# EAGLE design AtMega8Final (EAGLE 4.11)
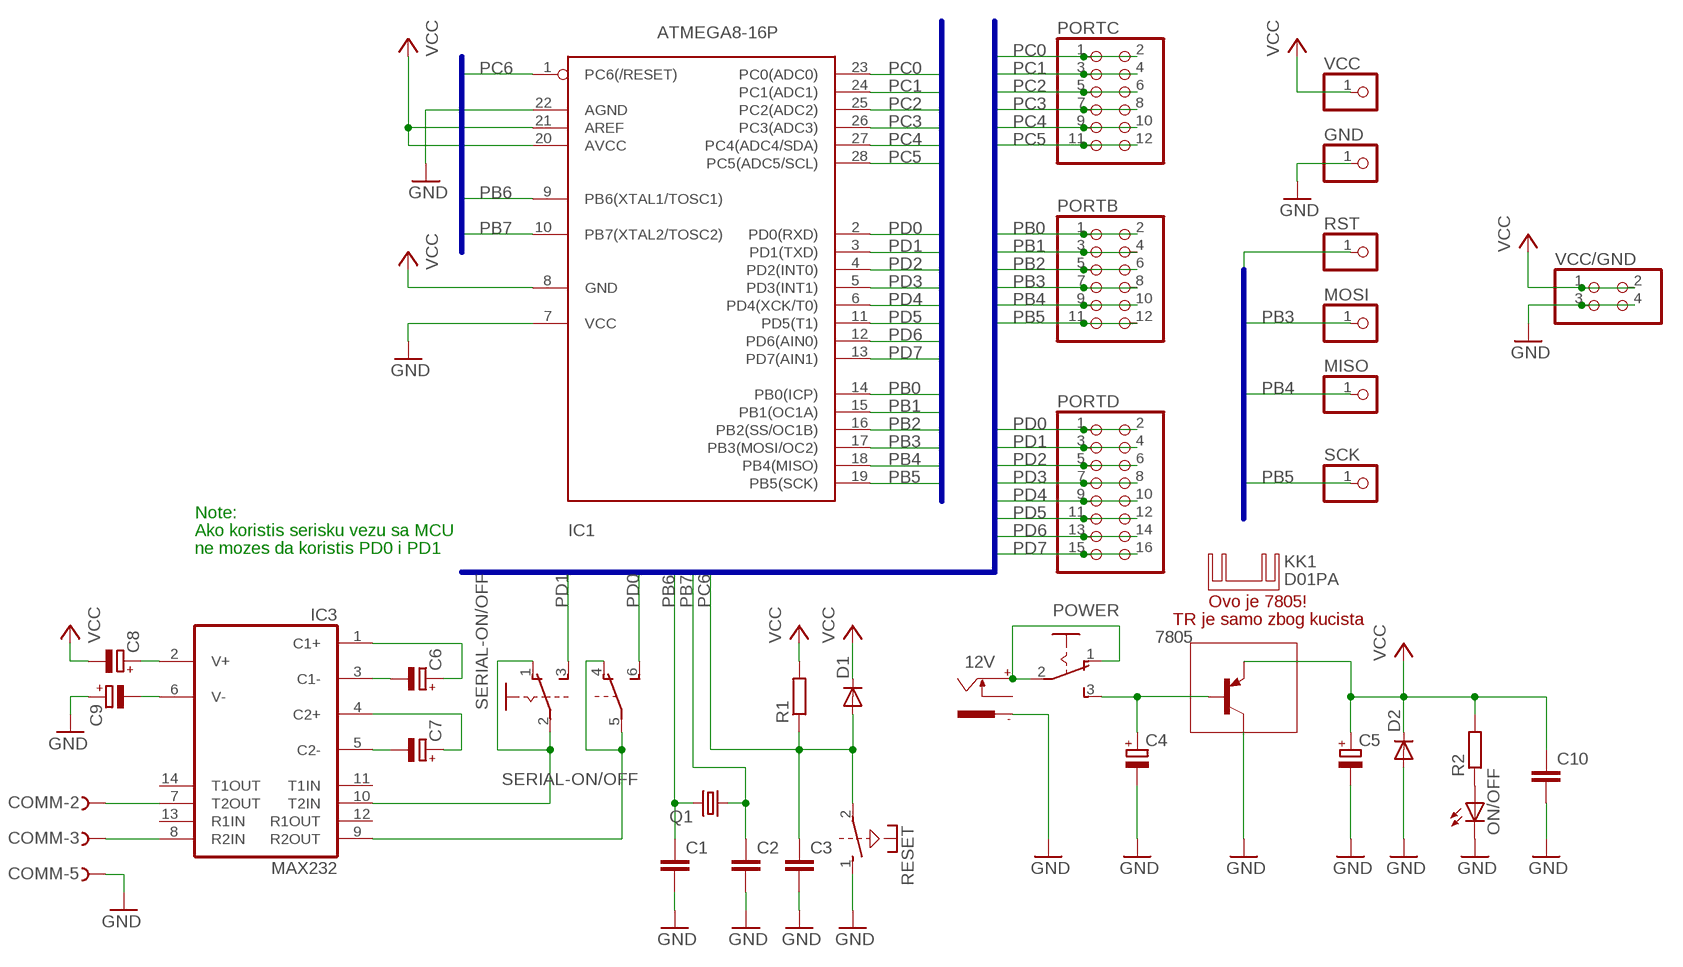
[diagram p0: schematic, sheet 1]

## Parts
12V  737992-55  [737992-5]
7805  -PNP-TO220V  [TO220V]
C1  C-EU025-025X050  [C025-025X050]
C2  C-EU025-025X050  [C025-025X050]
C3  C-EU025-025X050  [C025-025X050]
C4  CPOL-EUE5-6  [E5-6]
C5  CPOL-EUE5-6  [E5-6]
C6  CPOL-EUE5-6  [E5-6]
C7  CPOL-EUE5-6  [E5-6]
C8  CPOL-EUE5-6  [E5-6]
C9  CPOL-EUE5-6  [E5-6]
C10  C-EU025-025X050  [C025-025X050]
COMM  F09HPS  [F09HP]
D1  DIODE-DO35-10  [DO35-10]
D2  DIODE-DO34-7  [DO34-7]
GND  PINHD-1X1  [1X01]
IC1  ATMEGA8-16P  [DIL28-3]
IC3  MAX232  [DIL16]
KK1  D01PA  [D01PA]
MISO  PINHD-1X1  [1X01]
MOSI  PINHD-1X1  [1X01]
ON/OFF  LED5MM  [LED5MM]
PORTB  PINHD-2X6  [2X06]
PORTC  PINHD-2X6  [2X06]
PORTD  PINHD-2X8  [2X08]
POWER  255SB  [255SB]
Q1  CRYTALHC49U70  [HC49U70]
R1  R-EU_0204/7  [0204/7]
R2  R-EU_0204/7  [0204/7]
RESET  PVA1R  [PVA1R]
RST  PINHD-1X1  [1X01]
SCK  PINHD-1X1  [1X01]
SERIAL-ON/OFF  A68-A31  [A68-A31]
VCC  PINHD-1X1  [1X01]
VCC/GND  PINHD-2X2  [2X02]

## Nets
GND: 12V.-1 7805.2(C) C1.2 C2.2 C3.2 C4.- C5.- C9.+ C10.2 COMM.5 D2.A GND.1 IC1.7(VCC) IC1.22(AGND) ON/OFF.K(C) RESET.1(1:S) VCC/GND.3 VCC/GND.4
N$4: 12V.+ POWER.1(O) POWER.2(P)
N$5: 7805.1(B) C4.+ POWER.3(S)
N$6: ON/OFF.A R2.1
N$7: C6.- IC3.3(C1-)
N$8: C6.+ IC3.1(C1+)
N$9: C7.+ IC3.4(C2+)
N$10: C7.- IC3.5(C2-)
N$11: C8.+ IC3.2(V+)
N$12: C9.- IC3.6(V-)
N$13: IC3.9(R2OUT) SERIAL-ON/OFF.4(B:O) SERIAL-ON/OFF.5(B:P)
N$16: IC3.10(T2IN) SERIAL-ON/OFF.1(A:O) SERIAL-ON/OFF.2(A:P)
N$19: COMM.2 IC3.7(T2OUT)
N$20: COMM.3 IC3.8(R2IN)
PB0: IC1.14(PB0(ICP)) PORTB.1 PORTB.2
PB1: IC1.15(PB1(OC1A)) PORTB.3 PORTB.4
PB2: IC1.16(PB2(SS/OC1B)) PORTB.5 PORTB.6
PB3: IC1.17(PB3(MOSI/OC2)) MOSI.1 PORTB.7 PORTB.8
PB4: IC1.18(PB4(MISO)) MISO.1 PORTB.9 PORTB.10
PB5: IC1.19(PB5(SCK)) PORTB.11 PORTB.12 SCK.1
PB6: C1.1 IC1.9(PB6(XTAL1/TOSC1)) Q1.2
PB7: C2.1 IC1.10(PB7(XTAL2/TOSC2)) Q1.1
PC0: IC1.23(PC0(ADC0)) PORTC.1 PORTC.2
PC1: IC1.24(PC1(ADC1)) PORTC.3 PORTC.4
PC2: IC1.25(PC2(ADC2)) PORTC.5 PORTC.6
PC3: IC1.26(PC3(ADC3)) PORTC.7 PORTC.8
PC4: IC1.27(PC4(ADC4/SDA)) PORTC.9 PORTC.10
PC5: IC1.28(PC5(ADC5/SCL)) PORTC.11 PORTC.12
PC6: C3.1 D1.A IC1.1(PC6(/RESET)) R1.1 RESET.2(1:P) RST.1
PD0: IC1.2(PD0(RXD)) PORTD.1 PORTD.2 SERIAL-ON/OFF.6(B:S)
PD1: IC1.3(PD1(TXD)) PORTD.3 PORTD.4 SERIAL-ON/OFF.3(A:S)
PD2: IC1.4(PD2(INT0)) PORTD.5 PORTD.6
PD3: IC1.5(PD3(INT1)) PORTD.7 PORTD.8
PD4: IC1.6(PD4(XCK/T0)) PORTD.9 PORTD.10
PD5: IC1.11(PD5(T1)) PORTD.11 PORTD.12
PD6: IC1.12(PD6(AIN0)) PORTD.13 PORTD.14
PD7: IC1.13(PD7(AIN1)) PORTD.15 PORTD.16
VCC: 7805.3(E) C5.+ C8.- C10.1 D1.C D2.C IC1.8(GND) IC1.20(AVCC) IC1.21(AREF) R1.2 R2.2 VCC.1 VCC/GND.1 VCC/GND.2
Unconnected: 12V.-2 12V.K COMM.1 COMM.4 COMM.6 COMM.7 COMM.8 COMM.9 IC3.11(T1IN) IC3.12(R1OUT) IC3.13(R1IN) IC3.14(T1OUT) RESET.3(2:S) RESET.4(2:P)

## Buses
B$1
B$2
B$3
B$4

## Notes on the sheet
- Note:
- Ako koristis serisku vezu sa MCU
- ne mozes da koristis PD0 i PD1
- Ovo je 7805!
- TR je samo zbog kucista

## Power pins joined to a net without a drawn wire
GND: IC3.15(GND)
VCC: IC3.16(VCC)

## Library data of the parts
12V = con-conrad:737992-55: FEMALE PRINT CONNECTOR DIN 45323 (34V/3A), ROKA, distributor Conrad
7805 = transistor:*-PNP-: PNP Transistror
C1-C3 C10 = rcl:C-EU: CAPACITOR, European symbol
C4-C9 = rcl:CPOL-EU: POLARIZED CAPACITOR, European symbol
COMM = con-subd:F09?S: SUB-D
D1 D2 = diode:DIODE-: DIODE
GND MISO MOSI RST SCK VCC = pinhead:PINHD-1X1: PIN HEADER
IC1 = avr:ATMEGA8*P: MICROCONTROLLER 8 Kbytes FLASH 1 kbytes SRAM 512 bytes EEPROM USART 4-channel 10 bit ADC 2-channel 8 bit ADC
IC3 = maxim:MAX232: RS232 TRANSEIVER
KK1 = heatsink:D01PA: HEATSINK
ON/OFF = led:LED: LED
PORTB PORTC = pinhead:PINHD-2X6: PIN HEADER
PORTD = pinhead:PINHD-2X8: PIN HEADER
POWER = switch:255SB: SLIDING SWITCH distributor Buerklin, 11G810
Q1 = crystal:CRYTAL: CRYSTAL
R1 R2 = rcl:R-EU_: RESISTOR, European symbol
RESET = switch-misc:PVA1R: ITT SWITCH
SERIAL-ON/OFF = switch:A68-A31: SLIDING SWITCH Siemens, distributor Buerklin, 11G766
VCC/GND = pinhead:PINHD-2X2: PIN HEADER

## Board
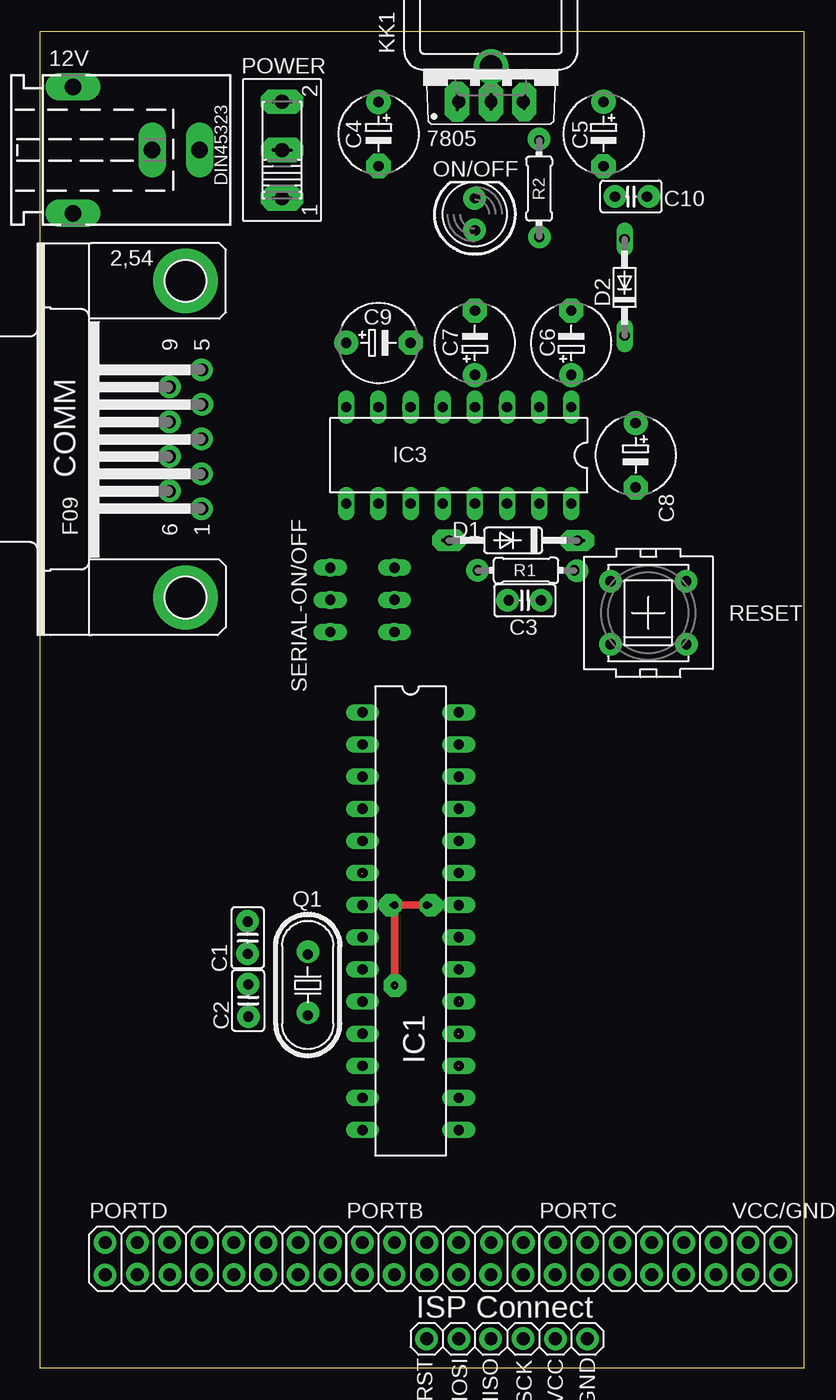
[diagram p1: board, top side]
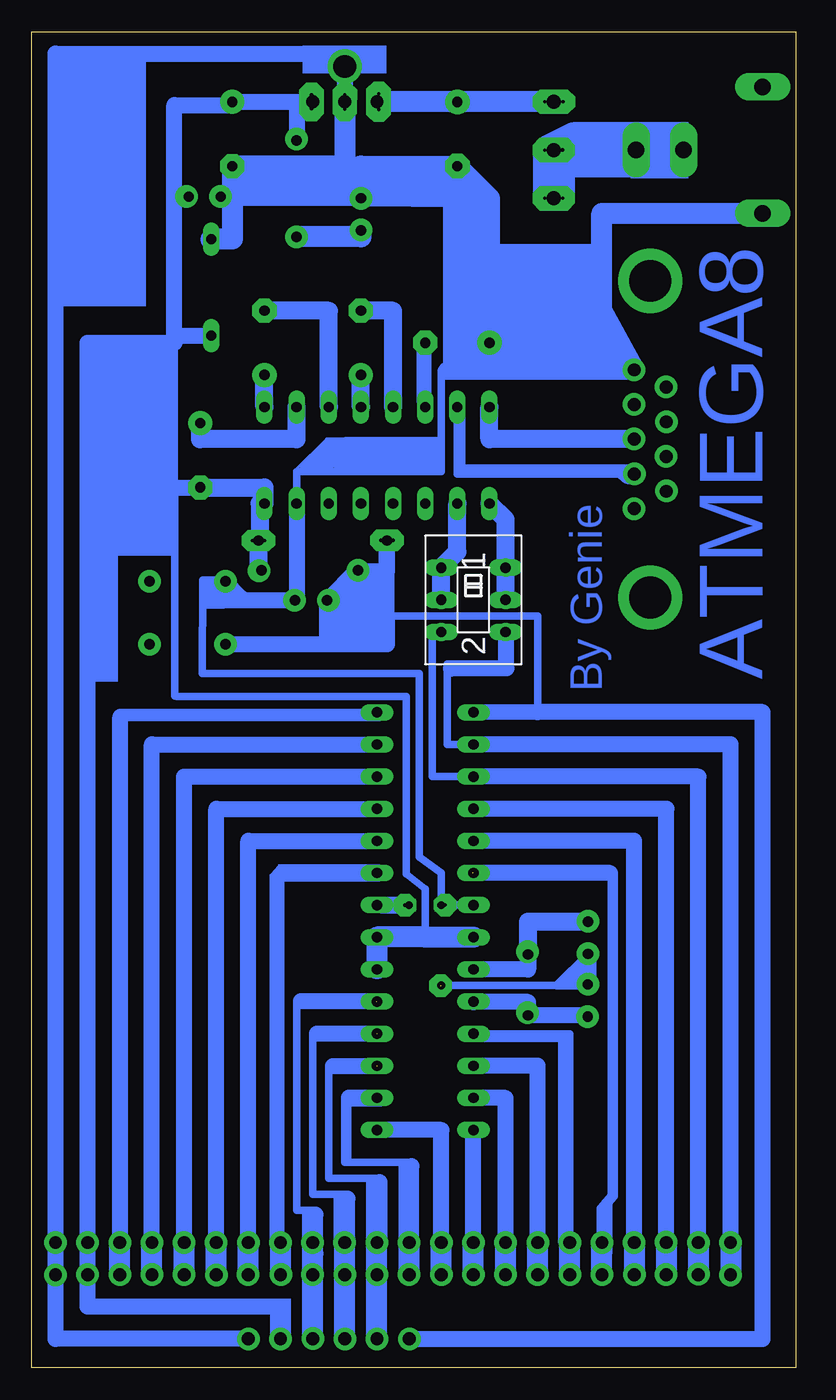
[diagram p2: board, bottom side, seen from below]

Size 60.4 x 105.63 mm. Coordinates in mm from the lower left corner, seen from the top.
Outline: 0,0 60.4,0 60.4,105.63 0,105.63 0,0
Copper layers (1*16): Top 0.035mm / dielectric 1.5mm / Bottom 0.035mm
Design rules "default": minimum track width 10mil, minimum drill 24mil, track to track 8mil, track to pad 8mil, pad to pad 8mil, via to via 8mil, smd to smd 8mil, copper to edge 40mil, drill to drill 8mil, minimum pad ring 10mil, minimum via ring 8mil, stop-mask expansion 4mil, vias tented up to drill 0mil, thermal gap 10mil
vRestrict: area 3.8,5.9 to 24.1,11.3; area 39.5,5.9 to 54.9,11.3; area 28.7,0.8 to 45,3.7

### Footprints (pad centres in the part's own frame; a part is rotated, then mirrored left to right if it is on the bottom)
737992-5 = drill 1.3 pad 2.184 long: + 0,10; -1 5,0; -2 -5,0; K 0,6.25
TO220V = drill 1.016 long: 1 -2.54,-2.54; 2 0,-2.54; 3 2.54,-2.54
C025-025X050 = drill 0.813 octagon: 1 -1.27,0; 2 1.27,0
E5-6 = drill 0.813 pad 1.905 round: + -2.54,0 | drill 0.813 pad 1.905 octagon: - 2.54,0
F09HP = drill 1.016 octagon: 1 -5.486,-1.27; 2 -2.743,-1.27; 3 0,-1.27; 4 2.743,-1.27; 5 5.486,-1.27; 6 -4.115,1.27; 7 -1.372,1.27; 8 1.372,1.27; 9 4.115,1.27 | drill 3.302 pad 5.08 round: G1 -12.522,0; G2 12.522,0
DO35-10 = drill 0.813 long: A 5.08,0; C -5.08,0
DO34-7 = drill 0.813 long: A 3.81,0; C -3.81,0
1X01 = drill 1.016 octagon: 1 0,0
DIL28-3 = drill 0.813 long: 1 -16.51,-3.81; 2 -13.97,-3.81; 3 -11.43,-3.81; 4 -8.89,-3.81; 5 -6.35,-3.81; 6 -3.81,-3.81; 7 -1.27,-3.81; 8 1.27,-3.81; 9 3.81,-3.81; 10 6.35,-3.81; 11 8.89,-3.81; 12 11.43,-3.81; 13 13.97,-3.81; 14 16.51,-3.81; 15 16.51,3.81; 16 13.97,3.81; 17 11.43,3.81; 18 8.89,3.81; 19 6.35,3.81; 20 3.81,3.81; 21 1.27,3.81; 22 -1.27,3.81; 23 -3.81,3.81; 24 -6.35,3.81; 25 -8.89,3.81; 26 -11.43,3.81; 27 -13.97,3.81; 28 -16.51,3.81
DIL16 = drill 0.813 long: 1 -8.89,-3.81; 2 -6.35,-3.81; 3 -3.81,-3.81; 4 -1.27,-3.81; 5 1.27,-3.81; 6 3.81,-3.81; 7 6.35,-3.81; 8 8.89,-3.81; 9 8.89,3.81; 10 6.35,3.81; 11 3.81,3.81; 12 1.27,3.81; 13 -1.27,3.81; 14 -3.81,3.81; 15 -6.35,3.81; 16 -8.89,3.81
D01PA = drill 1.803 pad 2.54 round: B 0,-1.016
LED5MM = drill 0.813 octagon: A -1.27,0; K 1.27,0
2X06 = drill 1.016 octagon: 1 -6.35,-1.27; 2 -6.35,1.27; 3 -3.81,-1.27; 4 -3.81,1.27; 5 -1.27,-1.27; 6 -1.27,1.27; 7 1.27,-1.27; 8 1.27,1.27; 9 3.81,-1.27; 10 3.81,1.27; 11 6.35,-1.27; 12 6.35,1.27
2X08 = drill 1.016 octagon: 1 -8.89,-1.27; 2 -8.89,1.27; 3 -6.35,-1.27; 4 -6.35,1.27; 5 -3.81,-1.27; 6 -3.81,1.27; 7 -1.27,-1.27; 8 -1.27,1.27; 9 1.27,-1.27; 10 1.27,1.27; 11 3.81,-1.27; 12 3.81,1.27; 13 6.35,-1.27; 14 6.35,1.27; 15 8.89,-1.27; 16 8.89,1.27
255SB = drill 1.118 long: 1 -3.81,0; 2 0,0; 3 3.81,0
HC49U70 = drill 0.813 round: 1 -2.413,0; 2 2.413,0
0204/7 = drill 0.813 octagon: 1 -3.81,0; 2 3.81,0
PVA1R = drill 0.813 octagon: 1 -2.997,2.489; 2 -2.997,-2.489; 3 2.997,2.489; 4 2.997,-2.489
A68-A31 = drill 0.813 long: 1 -2.54,-2.54; 2 0,-2.54; 3 2.54,-2.54; 4 -2.54,2.54; 5 0,2.54; 6 2.54,2.54
2X02 = drill 1.016 octagon: 1 -1.27,-1.27; 2 -1.27,1.27; 3 1.27,-1.27; 4 1.27,1.27

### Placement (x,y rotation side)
12V  2.63,96.27 270 top
7805  35.65,102.62 0 top
C1  16.43,34 270 top
C2  16.46,29.04 90 top
C3  38.33,60.67 0 top
C4  26.76,97.54 270 top
C5  44.54,97.54 270 top
C6  42,81.03 90 top
C7  34.38,81.03 90 top
C8  47.08,72.14 270 top
C9  26.76,81.03 0 top
C10  46.72,92.59 180 top
COMM  11.52,73.41 90 top
D1  37.4,65.41 180 top
D2  46.21,85.41 90 top
GND  43.27,2.29 0 top
IC1  29.3,35.31 270 top
IC3  33.11,72.14 180 top
KK1  35.65,103.89 0 top
MISO  35.65,2.29 0 top
MOSI  33.11,2.29 0 top
ON/OFF  34.38,91.19 90 top
PORTB  31.84,8.64 0 top
PORTC  47.08,8.64 0 top
PORTD  14.06,8.64 0 top
POWER  19.14,96.27 90 top
Q1  21.17,30.27 90 top
R1  38.42,63.04 0 top
R2  39.46,93.22 90 top
RESET  48.09,59.68 0 top
RST  30.57,2.29 0 top
SCK  38.19,2.29 0 top
SERIAL-ON/OFF  25.49,60.71 270 bottom
VCC  40.73,2.29 0 top
VCC/GND  57.24,8.64 0 top

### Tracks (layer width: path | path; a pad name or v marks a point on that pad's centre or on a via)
GND  (via drill 0.25 pad 1.78, 0.61)  (1 unrouted)
  Top 0.61: v28.03,30.23 v28.03,36.58 v30.57,36.58
  Bottom 0.406: VCC/GND.3 VCC/GND.4
  Bottom 0.61: 35.65,95 34.38,95 | COMM.5 12.82,78.94 | IC3.15 39.46,70.87 28.03,70.87 28.03,78.57 24.22,78.57 24.22,78.9 | 44.54,92.53 44.71,92.53 | C3.2 39.6,60.64 39.46,60.64 | 45.06,62.2 45.06,62.17 RESET.1 45.2,62.17 45.2,62.27 46.87,62.27 46.91,54.9 29.77,54.9 29.79,40.39 28.03,39.12 v28.03,36.58 IC1.7 | 16.46,30.29 16.58,30.29 | 16.46,30.29 C2.2 | 16.43,30.29 16.46,30.29 | C1.2 18.93,30.23 v28.03,30.23 | v30.57,36.58 IC1.22
  Bottom 1.27: COMM.5 24.22,78.9 C9.+ | IC3.15 39.46,60.64 | C3.2 45.06,60.67 45.06,62.17 | C1.2 16.43,30.29 | GND.1 58.51,2.29 VCC/GND.3 VCC/GND.4 58.51,103.89 35.65,103.89 7805.2
  Bottom 1.676: 7805.2 35.65,95 C5.- 44.54,92.53 44.54,89.23 D2.A | 12V.-1 15.33,91.27 15.33,83.57 12.82,78.94 | C9.+ 24.22,92.46 C4.- 34.38,95 ON/OFF.K | C10.2 44.71,92.59 44.71,92.53
  other vias: 28.08,30.21
N$1
  Bottom 1.27: 45.11,62.15 45.11,62.11 43.86,60.87
N$2
  Bottom 1.27: 34.63,63.07 34.66,63.07 36.98,60.74
N$3
  Bottom 1.27: 12.69,70.51 13.32,70.51 13.57,70.77
N$4
  Bottom 1.27: POWER.1 19.07,92.46 19.05,92.47 19.14,92.56 POWER.2
  Bottom 1.676: 12V.+ POWER.2
N$5
  Bottom 1.676: POWER.3 C4.+ 7805.1
N$6
  Bottom 0.61: ON/OFF.A 34.38,89.41
  Bottom 1.676: 34.37,89.92 ON/OFF.A | 34.38,89.41 R2.1
N$7
  Bottom 1.422: C6.- 36.92,83.57 IC3.3
N$8
  Bottom 1.422: IC3.1 C6.+
N$9
  Bottom 1.422: IC3.4 C7.+
N$10
  Bottom 1.422: C7.- 31.84,83.57 IC3.5
N$11
  Bottom 1.422: IC3.2 39.46,73.41 47.08,73.41 C8.+
N$12
  Bottom 1.016: IC3.6 C9.-
N$13
  Bottom 0.61: IC3.9
  Bottom 1.422: SERIAL-ON/OFF.5 SERIAL-ON/OFF.4 22.95,67.06 IC3.9
N$14
  Bottom 1.27: 29.81,92.44 34.49,92.44 34.49,92.49
N$15
  Bottom 1.27: 53.49,9.89 53.4,9.89 53.4,51.46
N$16
  Bottom 0.61: IC3.10 26.71,68.33
  Bottom 1.422: IC3.10 26.76,64.52 SERIAL-ON/OFF.1 SERIAL-ON/OFF.2
N$17
  Bottom 1.27: 22.91,58.09 22.88,58.09 22.88,55.3 27.25,55.3 27.25,55.27
N$18
  Bottom 1.27: 28.66,72.94 35.64,72.94 37.16,71.41
N$19
  Bottom 0.61: COMM.2 26.76,70.67 IC3.7
N$20
  Bottom 1.422: COMM.3 24.22,73.41 IC3.8
N$21
  Bottom 1.27: 19.18,96.26 17.61,97.82 12.49,97.82
N$22
  Bottom 1.27: 19.18,96.21 17.7,94.73 12.74,94.73
N$23  (via drill 0.25 pad 1.78)
  other vias: 2.62,101.3
N$24  (via drill 0.25 pad 1.78)
  other vias: 2.6,91.28
N$25  (via drill 0.25 pad 1.78)
  other vias: 8.87,96.29
N$26  (via drill 0.25 pad 1.78)
  other vias: 12.63,96.28
N$27  (via drill 0.25 pad 1.93)
  other vias: 18.45,96.27
N$28  (via drill 0.25 pad 1.93)
  other vias: 19.86,96.27
N$29  (via drill 0.25 pad 1.93)
  other vias: 19.12,96.27
N$30  (via drill 0.25 pad 1.93)
  other vias: 18.42,100.09
N$31  (via drill 0.25 pad 1.93)
  other vias: 19.85,100.09
N$32  (via drill 0.25 pad 1.93)
  other vias: 19.13,100.09
N$33  (via drill 0.25 pad 1.93)
  other vias: 19.85,92.46
N$34  (via drill 0.25 pad 1.93)
  other vias: 18.43,92.45
N$35  (via drill 0.25 pad 1.93)
  other vias: 19.11,92.45
N$36  (via drill 0.25 pad 1.93)
  other vias: 26.76,100.08
N$37  (via drill 0.25 pad 1.93)
  other vias: 26.76,95
N$38  (via drill 0.25 pad 1.93)
  other vias: 32.98,100.71
N$39  (via drill 0.25 pad 1.93)
  other vias: 32.98,99.48
N$40  (via drill 0.25 pad 1.93)
  other vias: 32.98,100.17
N$41  (via drill 0.25 pad 1.93)
  other vias: 35.65,100.64
N$42  (via drill 0.25 pad 1.93)
  other vias: 35.66,99.52
N$43  (via drill 0.25 pad 1.93)
  other vias: 35.66,100.12
N$44  (via drill 0.25 pad 1.93)
  other vias: 38.28,100.64
N$45  (via drill 0.25 pad 1.93)
  other vias: 38.28,99.53
N$46  (via drill 0.25 pad 1.93)
  other vias: 38.28,100.1
N$47  (via drill 0.25 pad 1.78)
  other vias: 39.46,97.15
N$48  (via drill 0.25 pad 1.78)
  other vias: 44.53,100.1
N$49  (via drill 0.25 pad 1.78)
  other vias: 44.54,94.98
N$50  (via drill 0.25 pad 1.78)
  other vias: 45.46,92.61
N$51  (via drill 0.25 pad 1.78)
  other vias: 48.14,92.59
N$52  (via drill 0.25 pad 1.78)
  other vias: 34.37,92.45
N$53  (via drill 0.25 pad 1.78)
  other vias: 34.37,89.97
N$54  (via drill 0.25 pad 1.78)
  other vias: 39.48,89.41
N$55  (via drill 0.25 pad 1.78)
  other vias: 24.22,81.03
N$56  (via drill 0.25 pad 1.78)
  other vias: 29.29,81.01
N$57  (via drill 0.25 pad 1.78)
  other vias: 34.39,83.58
N$58  (via drill 0.25 pad 1.78)
  other vias: 41.99,83.59
N$59  (via drill 0.25 pad 1.78)
  other vias: 41.99,78.51
N$60  (via drill 0.25 pad 1.78)
  other vias: 34.39,78.48
N$61  (via drill 0.25 pad 1.78)
  other vias: 12.79,78.91
N$62  (via drill 0.25 pad 1.78)
  other vias: 12.78,73.43
N$63  (via drill 0.25 pad 1.78)
  other vias: 12.78,70.67
N$64  (via drill 0.25 pad 1.78)
  other vias: 12.79,67.91
N$65  (via drill 0.25 pad 1.78)
  other vias: 10.24,69.32
N$66  (via drill 0.25 pad 1.78)
  other vias: 10.25,72.07
N$67  (via drill 0.25 pad 1.78)
  other vias: 10.24,74.79
N$68  (via drill 0.25 pad 1.78)
  other vias: 10.26,77.54
N$69  (via drill 0.25 pad 1.78)
  other vias: 12.81,76.16
N$70  (via drill 0.25 pad 1.78)
  other vias: 47.1,74.69
N$71  (via drill 0.25 pad 1.78)
  other vias: 47.1,69.64
N$72  (via drill 0.25 pad 1.78)
  other vias: 51.08,62.19
N$73  (via drill 0.25 pad 1.78)
  other vias: 51.09,57.19
N$74  (via drill 0.25 pad 1.78)
  other vias: 45.08,57.2
N$75  (via drill 0.25 pad 1.78)
  other vias: 45.08,62.18
N$76  (via drill 0.25 pad 1.78)
  other vias: 42.43,63.02
N$77  (via drill 0.25 pad 1.78)
  other vias: 34.6,63.03
N$78  (via drill 0.25 pad 1.78)
  other vias: 36.94,60.67
N$79  (via drill 0.25 pad 1.78)
  other vias: 39.61,60.68
N$80  (via drill 0.3 pad 2.54)
  other vias: 35.65,102.89
N$81  (via drill 0.25 pad 1.78)
  other vias: 5.16,9.91
N$82  (via drill 0.25 pad 1.78)
  other vias: 5.16,7.35
N$83  (via drill 0.25 pad 1.78)
  other vias: 7.7,9.91
N$84  (via drill 0.25 pad 1.78)
  other vias: 7.71,7.41
N$85  (via drill 0.25 pad 1.78)
  other vias: 10.27,7.38
N$86  (via drill 0.25 pad 1.78)
  other vias: 10.26,9.93
N$87  (via drill 0.25 pad 1.78)
  other vias: 12.8,9.91
N$88  (via drill 0.25 pad 1.78)
  other vias: 12.78,7.36
N$89  (via drill 0.25 pad 1.78)
  other vias: 15.33,7.37
N$90  (via drill 0.25 pad 1.78)
  other vias: 15.32,9.92
N$91  (via drill 0.25 pad 1.78)
  other vias: 17.86,9.91
N$92  (via drill 0.25 pad 1.78)
  other vias: 17.85,7.36
N$93  (via drill 0.25 pad 1.78)
  other vias: 20.41,7.38
N$94  (via drill 0.25 pad 1.78)
  other vias: 20.4,9.91
N$95  (via drill 0.25 pad 1.78)
  other vias: 22.97,9.91
N$96  (via drill 0.25 pad 1.78)
  other vias: 22.94,7.38
N$97  (via drill 0.25 pad 1.78)
  other vias: 25.49,7.38
N$98  (via drill 0.25 pad 1.78)
  other vias: 25.49,9.91
N$99  (via drill 0.25 pad 1.78)
  other vias: 28.03,9.92
N$100  (via drill 0.25 pad 1.78)
  other vias: 28,7.37
N$101  (via drill 0.25 pad 1.78)
  other vias: 30.58,7.37
N$102  (via drill 0.25 pad 1.78)
  other vias: 30.59,9.92
N$103  (via drill 0.25 pad 1.78)
  other vias: 33.1,9.91
N$104  (via drill 0.25 pad 1.78)
  other vias: 33.1,7.37
N$105  (via drill 0.25 pad 1.78)
  other vias: 35.63,7.36
N$106  (via drill 0.25 pad 1.78)
  other vias: 35.67,9.89
N$107  (via drill 0.25 pad 1.78)
  other vias: 38.21,9.91
N$108  (via drill 0.25 pad 1.78)
  other vias: 38.2,7.39
N$109  (via drill 0.25 pad 1.78)
  other vias: 40.73,9.9
N$110  (via drill 0.25 pad 1.78)
  other vias: 40.71,7.38
N$111  (via drill 0.25 pad 1.78)
  other vias: 43.3,7.38
N$112  (via drill 0.25 pad 1.78)
  other vias: 43.27,9.92
N$113  (via drill 0.25 pad 1.78)
  other vias: 45.83,9.9
N$114  (via drill 0.25 pad 1.78)
  other vias: 45.8,7.35
N$115  (via drill 0.25 pad 1.78)
  other vias: 48.35,9.92
N$116  (via drill 0.25 pad 1.78)
  other vias: 48.35,7.38
N$117  (via drill 0.25 pad 1.78)
  other vias: 50.9,9.92
N$118  (via drill 0.25 pad 1.78)
  other vias: 50.88,7.38
N$119  (via drill 0.25 pad 1.78)
  other vias: 53.44,7.37
N$120  (via drill 0.25 pad 1.78)
  other vias: 53.44,9.9
N$121  (via drill 0.25 pad 1.78)
  other vias: 30.56,2.29
N$122  (via drill 0.25 pad 1.78)
  other vias: 33.12,2.28
N$123  (via drill 0.25 pad 1.78)
  other vias: 35.63,2.3
N$124  (via drill 0.25 pad 1.78)
  other vias: 38.18,2.32
N$125  (via drill 0.25 pad 1.78)
  other vias: 40.73,2.3
N$126  (via drill 0.25 pad 1.78)
  other vias: 43.27,2.27
N$127  (via drill 0.25 pad 1.78)
  other vias: 27.72,36.6
N$128  (via drill 0.25 pad 1.78)
  other vias: 30.9,36.58
N$129  (via drill 0.25 pad 1.78)
  other vias: 21.2,32.91
N$130  (via drill 0.25 pad 1.78)
  other vias: 21.2,28.07
N$131  (via drill 0.25 pad 1.78)
  other vias: 16.49,27.78
N$132  (via drill 0.25 pad 1.78)
  other vias: 16.45,30.32
N$133  (via drill 0.25 pad 1.78)
  other vias: 16.43,32.74
N$134  (via drill 0.25 pad 1.78)
  other vias: 16.43,35.3
N$135  (via drill 0.25 pad 1.42)
  other vias: 22.95,60.71
N$136  (via drill 0.25 pad 1.42)
  other vias: 22.95,63.27
N$137  (via drill 0.25 pad 1.42)
  other vias: 22.94,58.18
N$138  (via drill 0.25 pad 1.42)
  other vias: 28.02,58.17
N$139  (via drill 0.25 pad 1.42)
  other vias: 28.04,60.71
N$140  (via drill 0.25 pad 1.42)
  other vias: 28.04,63.25
N$141  (via drill 0.25 pad 1.68)
  other vias: 31.84,65.41
N$142  (via drill 0.25 pad 1.68)
  other vias: 32.81,65.41
N$143  (via drill 0.25 pad 1.68)
  other vias: 32.33,65.41
N$144  (via drill 0.25 pad 1.68)
  other vias: 42,65.4
N$145  (via drill 0.25 pad 1.68)
  other vias: 42.97,65.4
N$146  (via drill 0.25 pad 1.68)
  other vias: 42.48,65.4
N$147  (via drill 0.25 pad 1.27)
  other vias: 24.23,75.95
N$148  (via drill 0.25 pad 1.27)
  other vias: 26.76,75.96
N$149  (via drill 0.25 pad 1.27)
  other vias: 29.28,75.95
N$150  (via drill 0.25 pad 1.27)
  other vias: 31.82,75.96
N$151  (via drill 0.25 pad 1.27)
  other vias: 34.37,75.94
N$152  (via drill 0.25 pad 1.27)
  other vias: 36.91,75.93
N$153  (via drill 0.25 pad 1.27)
  other vias: 39.45,75.94
N$154  (via drill 0.25 pad 1.27)
  other vias: 42.01,75.94
N$155  (via drill 0.25 pad 1.27)
  other vias: 24.23,68.34
N$156  (via drill 0.25 pad 1.27)
  other vias: 26.76,68.31
N$157  (via drill 0.25 pad 1.27)
  other vias: 29.3,68.34
N$158  (via drill 0.25 pad 1.27)
  other vias: 31.84,68.34
N$159  (via drill 0.25 pad 1.27)
  other vias: 34.38,68.32
N$160  (via drill 0.25 pad 1.27)
  other vias: 36.92,68.32
N$161  (via drill 0.25 pad 1.27)
  other vias: 39.47,68.34
N$162  (via drill 0.25 pad 1.27)
  other vias: 42.01,68.32
N$163  (via drill 0.81 pad 3.81)
  other vias: 11.5,60.92
N$164  (via drill 0.81 pad 3.81)
  other vias: 11.52,85.93
N$165
  Bottom 1.27: 27.7,78.79 27.38,79.11 27.32,79.11
N$166  (via drill 0.25 pad 1.02)
  other vias: 25.5,51.83
N$167  (via drill 0.25 pad 1.02)
  other vias: 25.49,46.72
N$168  (via drill 0.25 pad 1.02)
  other vias: 25.49,44.17
N$169  (via drill 0.25 pad 1.02)
  other vias: 25.51,41.65
N$170  (via drill 0.25 pad 1.02)  (1 unrouted)
  Bottom 1.27: 14.69,39.11 25.53,39.11
  other vias: 25.49,39.1
N$171  (via drill 0.25 pad 1.02)
  other vias: 25.48,36.59
N$172  (via drill 0.25 pad 1.02)
  other vias: 25.47,34.07
N$173  (via drill 0.25 pad 1.02)
  other vias: 25.49,31.48
N$174  (via drill 0.25 pad 1.02)
  other vias: 25.49,28.95
N$175  (via drill 0.25 pad 1.02)
  other vias: 25.49,26.41
N$176  (via drill 0.25 pad 1.02)
  other vias: 25.47,23.89
N$177  (via drill 0.25 pad 1.02)
  other vias: 25.49,21.37
N$178  (via drill 0.25 pad 1.02)
  other vias: 25.49,18.8
N$179  (via drill 0.25 pad 1.02)
  other vias: 33.08,18.77
N$180  (via drill 0.25 pad 1.02)
  other vias: 33.13,21.34
N$181  (via drill 0.25 pad 1.02)  (1 unrouted)
  Bottom 1.27: 33.1,23.85 36.59,23.85
  other vias: 33.11,23.89
N$182  (via drill 0.25 pad 1.02)  (1 unrouted)
  Bottom 1.27: 33.08,26.4 37.86,26.4
  other vias: 33.11,26.44
N$183  (via drill 0.25 pad 1.02)  (1 unrouted)
  Bottom 1.27: 33.17,28.97 39.13,28.97
  other vias: 33.14,28.96
N$184  (via drill 0.25 pad 1.02)
  other vias: 33.11,31.53
N$185  (via drill 0.25 pad 1.02)
  other vias: 33.11,34.07
N$186  (via drill 0.25 pad 1.02)
  other vias: 33.08,36.58
N$187  (via drill 0.25 pad 1.02)
  other vias: 33.08,39.13
N$188  (via drill 0.25 pad 1.02)
  other vias: 33.1,41.66
N$189  (via drill 0.25 pad 1.02)
  other vias: 33.1,44.2
N$190  (via drill 0.25 pad 1.02)
  other vias: 33.1,46.74
N$191  (via drill 0.25 pad 1.02)
  other vias: 33.1,49.27
N$192  (via drill 0.25 pad 1.02)
  other vias: 33.1,51.84
N$193  (via drill 0.25 pad 1.02)
  other vias: 46.21,89.2
N$194  (via drill 0.25 pad 1.02)
  other vias: 46.19,81.59
N$195
  Bottom 0.254: 40.91,39.6 40.85,39.66
N$196
  Bottom 0.254: 40.86,39.65 41.46,38.96
N$197
  Bottom 0.254: 35.85,73.44 37.1,73.44 39.63,70.93
N$198
  Bottom 1.778: 36.72,72.48 36.8,72.48 37.73,71.55
N$199
  Bottom 1.27: 38.56,71.2 38.44,71.2
N$200
  Bottom 1.27: 17.68,97.83 19.82,96.75
N$201
  Bottom 1.27: 32.9,9.8 32.9,14.68
N$202
  Bottom 1.27: 35.45,10.11 35.45,13.39
N$203
  Bottom 1.27: 30.39,9.92 30.39,15.94
N$204
  Bottom 1.27: 38.04,9.02 37.98,9.04 37.98,12.13
N$205
  Bottom 1.27: 33.29,21.35 35.31,21.35
N$206  (via drill 0.25 pad 1.78)
  other vias: 55.98,7.38
N$207  (via drill 0.25 pad 1.78)
  other vias: 55.97,9.9
N$208  (via drill 0.25 pad 1.78)
  other vias: 58.52,9.91
N$209  (via drill 0.25 pad 1.78)
  other vias: 58.52,7.35
PB0
  Bottom 1.27: PORTB.2 IC1.14
  Bottom 1.676: PORTB.1 PORTB.2
PB1
  Bottom 1.27: PORTB.4 28.03,18.8 IC1.15
  Bottom 1.676: PORTB.3 PORTB.4
PB2
  Bottom 0.61: PORTB.6 30.57,16.26 35.65,16.26 35.65,21.34 IC1.16
  Bottom 1.676: PORTB.5 PORTB.6
PB3
  Bottom 0.61: PORTB.8 33.11,14.99 36.92,14.99 36.92,23.88 IC1.17
  Bottom 1.676: MOSI.1 PORTB.7 PORTB.8
PB4
  Bottom 0.61: PORTB.10 35.65,13.72 38.19,13.72 38.19,26.42 IC1.18
  Bottom 1.676: MISO.1 PORTB.9 PORTB.10
PB5
  Bottom 0.61: IC1.19 39.46,28.96 39.46,12.45 38.19,12.45 PORTB.12
  Bottom 1.676: SCK.1 PORTB.11 PORTB.12
PB6
  Bottom 0.61: Q1.2 | 25.49,31.49 IC1.9
  Bottom 1.27: Q1.2 21.17,31.49 25.49,31.49
  Bottom 1.422: C1.1 21.18,35.27 Q1.2
PB7
  Bottom 0.61: Q1.1 | C2.1 16.46,27.87 | 25.49,28.92 IC1.10
  Bottom 1.27: 16.46,27.87 Q1.1 | Q1.1 21.17,28.92 25.49,28.92
PC0
  Bottom 0.61: PORTC.2 40.73,39.12 IC1.23
  Bottom 1.676: PORTC.1 PORTC.2
PC1
  Bottom 1.27: IC1.24 43.27,41.66 PORTC.4
  Bottom 1.676: PORTC.3 PORTC.4
PC2
  Bottom 1.27: PORTC.6 45.81,44.2 IC1.25
  Bottom 1.676: PORTC.5 PORTC.6
PC3
  Bottom 1.27: PORTC.8 48.35,46.74 IC1.26
  Bottom 1.676: PORTC.7 PORTC.8
PC4
  Bottom 1.27: IC1.27 50.89,49.28 PORTC.10
  Bottom 1.676: PORTC.9 PORTC.10
PC5
  Bottom 0.61: IC1.28 53.43,51.82 PORTC.12
  Bottom 1.676: PORTC.11 PORTC.12
PC6
  Bottom 0.61: 45.11,57.2 RESET.2 | 37.06,57.2 37.06,57.25 | 34.61,62.96 R1.1 | 32.32,59.44 20.41,59.44 20.41,51.83 | IC1.1
  Bottom 1.27: RESET.2 37.06,57.2 32.32,57.2 32.32,59.44 D1.A 32.32,62.96 34.61,62.96 | 37.06,57.25 C3.1 | IC1.1 20.41,51.83 2.63,51.85 2.63,2.29 RST.1
PD0  (via drill 0.25 pad 1.02)
  Bottom 0.61: SERIAL-ON/OFF.6 22.95,55.63 27.57,55.63 27.57,49.28 v25.51,49.28 IC1.2
  Bottom 1.27: PORTD.2 5.17,49.28 IC1.2
  Bottom 1.676: PORTD.2 PORTD.1
PD1
  Bottom 0.61: IC1.3 28.74,46.74 28.74,58.17 SERIAL-ON/OFF.3
  Bottom 1.27: PORTD.4 7.71,46.74 IC1.3
  Bottom 1.676: PORTD.4 PORTD.3
PD2
  Bottom 1.27: PORTD.6 10.25,44.2 IC1.4
  Bottom 1.676: PORTD.6 PORTD.5
PD3
  Bottom 1.27: PORTD.8 12.79,41.66 IC1.5
  Bottom 1.676: PORTD.8 PORTD.7
PD4
  Bottom 0.813: PORTD.10 15.33,12.57 14.5,13.6 14.46,39.12 IC1.6
  Bottom 1.676: PORTD.9 PORTD.10
PD5
  Bottom 0.61: PORTD.12 17.87,26.42 IC1.11
  Bottom 1.676: PORTD.11 PORTD.12
PD6
  Bottom 1.27: PORTD.14 20.41,23.88 IC1.12
  Bottom 1.676: PORTD.13 PORTD.14
PD7
  Bottom 1.27: PORTD.16 22.95,21.34 IC1.13
  Bottom 1.676: PORTD.15 PORTD.16
VCC
  Bottom 0.406: VCC/GND.1 VCC/GND.2
  Bottom 0.61: 49.1,69.6 49.11,69.6 49.11,69.78 | 49.11,69.78 49.11,81.03 49.11,81.59 | 44.54,100.33 C5.+ 44.54,99.83 | 49.11,92.48 48.94,92.48 48.94,92.59 | 49.11,69.78 49.12,69.78 | 42.37,65.29 42.37,65.41 D1.C 42.48,65.44 | IC3.16 42.37,68.33 | R1.2 42.27,63.04 42.27,63.01 42.17,63.01 | 49.1,69.6 48.97,69.72 | 49.1,69.6 49.1,53.13 48.94,53.09 30.82,53.09 30.82,39.04 29.3,37.85 29.3,34.05 29.3,34.04 | 33.15,34.05 IC1.21 | IC1.8 | IC1.20 33.11,31.56 33.15,31.56
  Bottom 1.27: 39.46,100.08 7805.3 | C5.+ 39.46,100.08 | 39.46,100.08 R2.2 | 49.1,69.6 C8.- | 44.54,99.83 49.11,99.83 49.11,92.48 49.11,81.59 D2.C | 48.94,92.59 C10.1 | VCC.1 40.73,4.83 55.97,4.83 VCC/GND.1 VCC/GND.2 55.97,81.03 49.11,81.03
  Bottom 1.422: C8.- 42,69.6 IC3.16 | 42.37,68.33 42.37,65.41 | 42.27,63.01 42.48,63.01 D1.C
  Bottom 1.676: IC1.8 29.3,34.05 IC1.21 | IC1.21 33.11,31.56
(copper drawn outside any net)
  shapes: Bottom area x46

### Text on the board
Bottom: ATMEGA8 | By Genie
tPlace: ISP Connect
